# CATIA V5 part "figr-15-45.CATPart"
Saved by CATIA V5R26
Part number: Part1
Bounding box of the stored display mesh (mm): x 2.5 to 37.676, y -21.475 to 20.775, z 0 to 35.904
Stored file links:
  D:\_Deepak\CATIA\CATIA V5 2015 Parts Files\Part files\Partfiles\c15_catia_v5_6r2015_prt\figr-15-45.CATPart
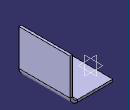
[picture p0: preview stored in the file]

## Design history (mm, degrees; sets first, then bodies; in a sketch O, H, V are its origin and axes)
SheetMetalParameters1: Thickness 2, BendRadius 4, KFactor 0.400515 {= log(min(100,max(20*SheetMetalParameters1.BendRadius,SheetMetalParameters1.Thickness)/SheetMetalParameters1.Thickness))/log(100)/2}, ReliefRadialLength 1, ReliefAxialLength 2, MinimumBendRadius 0
Body1 (main body)
  Sketch1 on xy-plane, origin (0, 0, 0), H (1, 0, 0), V (0, 1, 0)
    line L1 (2.4998, 20.7748) -> (69.1212, 20.7748)
    line L2 (69.1212, 20.7748) -> (69.1212, -21.4753)
    line L3 (69.1212, -21.4753) -> (2.4998, -21.4753)
    line L4 (2.4998, -21.4753) -> (2.4998, 20.7748)
    horizontal: L1 H, L3 H
    vertical: L2 V, L4 V
  Wall1: Thickness 2, Profile Sketch1
  Sketch2 on face of Wall1, origin (0, 0, 2), H (1, 0, 0), V (0, 1, 0)
    line L1 (35.4466, 20.5889) -> (35.4466, -21.306)
    vertical: L1 V
  FlatBend1: Angle 90, Axis Sketch2, FixedPoint vertex [face of Wall1 | face of Wall1 | face of Wall1], KFactor 0.400515 {= log(min(100,max(20*FlatBend1.FlatBendRadius,SheetMetalParameters1.Thickness)/SheetMetalParameters1.Thickness))/log(100)/2}, Radius 4 {= SheetMetalParameters1.BendRadius}
  Unfold1: FoldUnfold_Angles 90, FoldUnfold_FoldUnfoldFaces face of FlatBend1, FoldUnfold_ReferenceFaces face of Wall1
  Fold1: FoldUnfold_Angles 90, FoldUnfold_FoldUnfoldFaces face of FlatBend1, FoldUnfold_ReferenceFaces face of Wall1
